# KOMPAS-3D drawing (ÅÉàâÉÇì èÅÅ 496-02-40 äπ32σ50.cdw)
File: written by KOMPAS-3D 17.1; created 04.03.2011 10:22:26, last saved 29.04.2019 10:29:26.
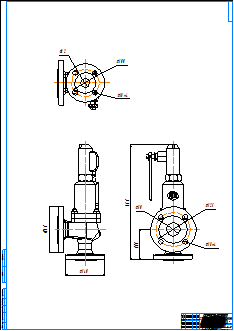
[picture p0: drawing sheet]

Sheet 1: A0, portrait

Title block, sheet 1: name: ПРЕГРАН КПП 496-02-40 / Ду32х50; material: Внимание! Данный продукт является объектом авторского права ООО «Торговый Дом АДЛ». / Запрещается изменение, копирование, распространение / (в том числе путем копирования на другие сайты и ресурсы в Интернете) / или любое иное использование информации и объектов без предварительного / согласия правообладателя (ООО «Торговый Дом АДЛ»).; scale: 1:1; sheets: 1; organisation: ООО "Торговый дом АДЛ"; sheet format: A0; stored path: C:\Users\tra\Desktop\2д чертежи\Предохранительные клапаны ПРЕГРАН\ПРЕГРАН 496\ПРЕГРАН КПП 496-02-40\KOMPAS 2D\ПРЕГРАН КПП 496-02-40 Ду32х50.cdw

Views: Спереди 1, Проекционный вид 2, Проекционный вид 3
Dimensions and other numbers on the sheet: 110; 125; 18; 50; 140; 165; 420; 100; 32; 1:1; 1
